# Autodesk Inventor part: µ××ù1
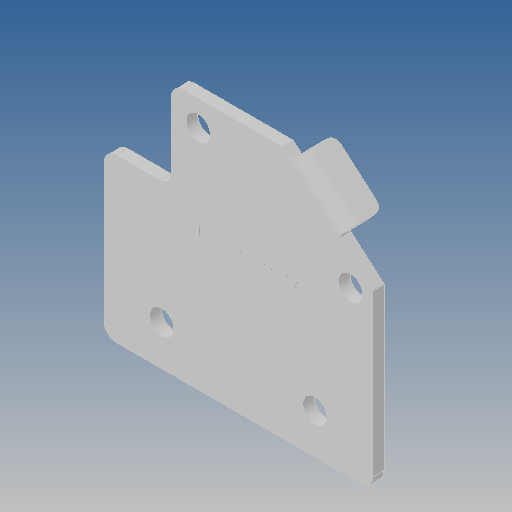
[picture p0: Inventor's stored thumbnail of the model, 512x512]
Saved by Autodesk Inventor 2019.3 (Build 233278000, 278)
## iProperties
Created: 2017-08
Part Number: µ××ù1
Material: Ogólny
Document SubType Name: Modeling
Designer: Admin
Density: 1 g/cm^3
Appearance: Domyślna
Author: Admin
Revision Number: ÈÎºÎ
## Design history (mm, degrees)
feature "ÊäÈë1"
node "Bryła1"
